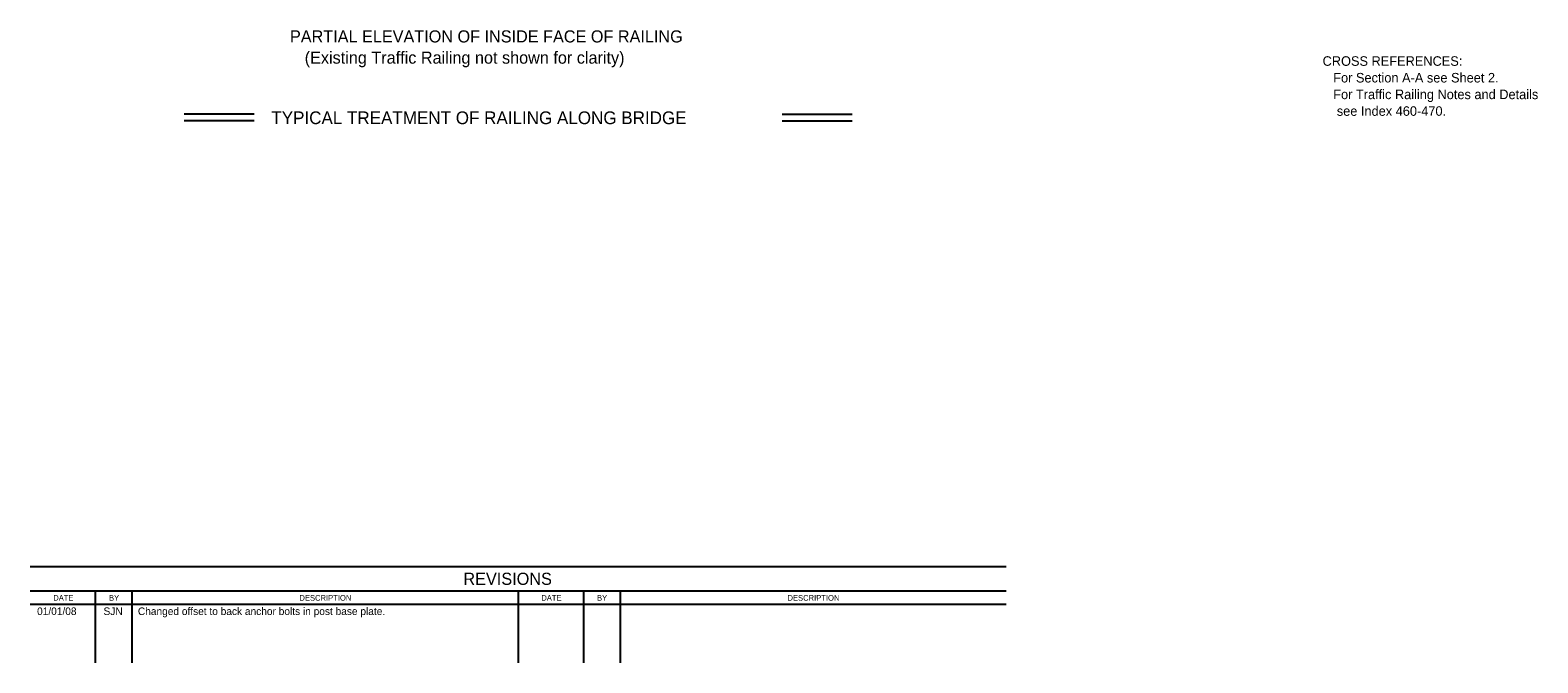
# Model space of a CAD drawing. Extents: x 21516.9 to 21589, y 56155.1 to 56195.
# Drawn here: x 21516.88 to 21548.71, y 56155.07 to 56168.43 of the extents above; entities that cross this region are included whole.
import ezdxf

# ---------------------------------------------------------------- set-up
doc = ezdxf.new("R2010")
doc.units = 0
for name, color, linetype in [('PlotBorder_dp', 7, 'Continuous'), ('SheetBorder_dp', 7, 'Continuous'), ('SheetLines_dp', 7, 'Continuous')]:
    doc.layers.add(name, color=color, linetype=linetype)

msp = doc.modelspace()

# ---------------------------------------------------------------- linework, layer by layer
at = {"layer": 'PlotBorder_dp'}
for p, q in [((21521.608, 56166.657), (21520.131, 56166.657)), ((21521.608, 56166.515), (21520.131, 56166.515)), ((21532.759, 56166.657), (21534.236, 56166.657)), ((21532.759, 56166.515), (21534.236, 56166.515))]:
    msp.add_line(p, q, dxfattribs=at)
at = {"layer": 'SheetLines_dp'}
for p, q in [((21537.488, 56157.1), (21516.877, 56157.1)), ((21537.488, 56156.585), (21516.877, 56156.585)), ((21518.253, 56156.585), (21518.253, 56155.07)), ((21519.027, 56156.585), (21519.027, 56155.07)), ((21527.183, 56156.585), (21527.183, 56155.07)), ((21528.559, 56156.585), (21528.559, 56155.07)), ((21529.333, 56156.585), (21529.333, 56155.07)), ((21516.877, 56156.312), (21537.488, 56156.312))]:
    msp.add_line(p, q, dxfattribs=at)

# ---------------------------------------------------------------- texts
at = {"layer": 'PlotBorder_dp'}
for s, height, p in [('PARTIAL ELEVATION OF INSIDE FACE OF RAILING', 0.256, (21522.363, 56168.172)), ('(Existing Traffic Railing not shown for clarity)', 0.256, (21522.674, 56167.724)), ('CROSS REFERENCES:', 0.2016, (21544.169, 56167.679)), ('   For Section A-A see Sheet 2.', 0.2016, (21544.169, 56167.327)), ('   For Traffic Railing Notes and Details ', 0.2016, (21544.169, 56166.975)), ('    see Index 460-470.', 0.2016, (21544.169, 56166.623))]:
    msp.add_text(s, height=height, dxfattribs=at).set_placement(p)
at = {"layer": 'SheetBorder_dp'}
for s, height, p in [('TYPICAL TREATMENT OF RAILING ALONG BRIDGE', 0.2688, (21521.97, 56166.447)), ('REVISIONS', 0.2567, (21526.025, 56156.717)), ('BY', 0.1201, (21518.541, 56156.383)), ('BY', 0.1201, (21528.847, 56156.383)), ('01/01/08', 0.16, (21517.023, 56156.08)), ('SJN', 0.16, (21518.426, 56156.08)), ('Changed offset to back anchor bolts in post base plate.', 0.16, (21519.152, 56156.08))]:
    msp.add_text(s, height=height, dxfattribs=at).set_placement(p)
for s, height, rotation, p in [('DATE', 0.1196, 359.8693, (21517.365, 56156.383)), ('DESCRIPTION', 0.12007, 0.0498, (21522.563, 56156.382)), ('DATE', 0.1196, 359.8693, (21527.671, 56156.383)), ('DESCRIPTION', 0.12007, 0.0498, (21532.869, 56156.382))]:
    msp.add_text(s, height=height, rotation=rotation, dxfattribs=at).set_placement(p)

doc.saveas('drawing.dxf')
